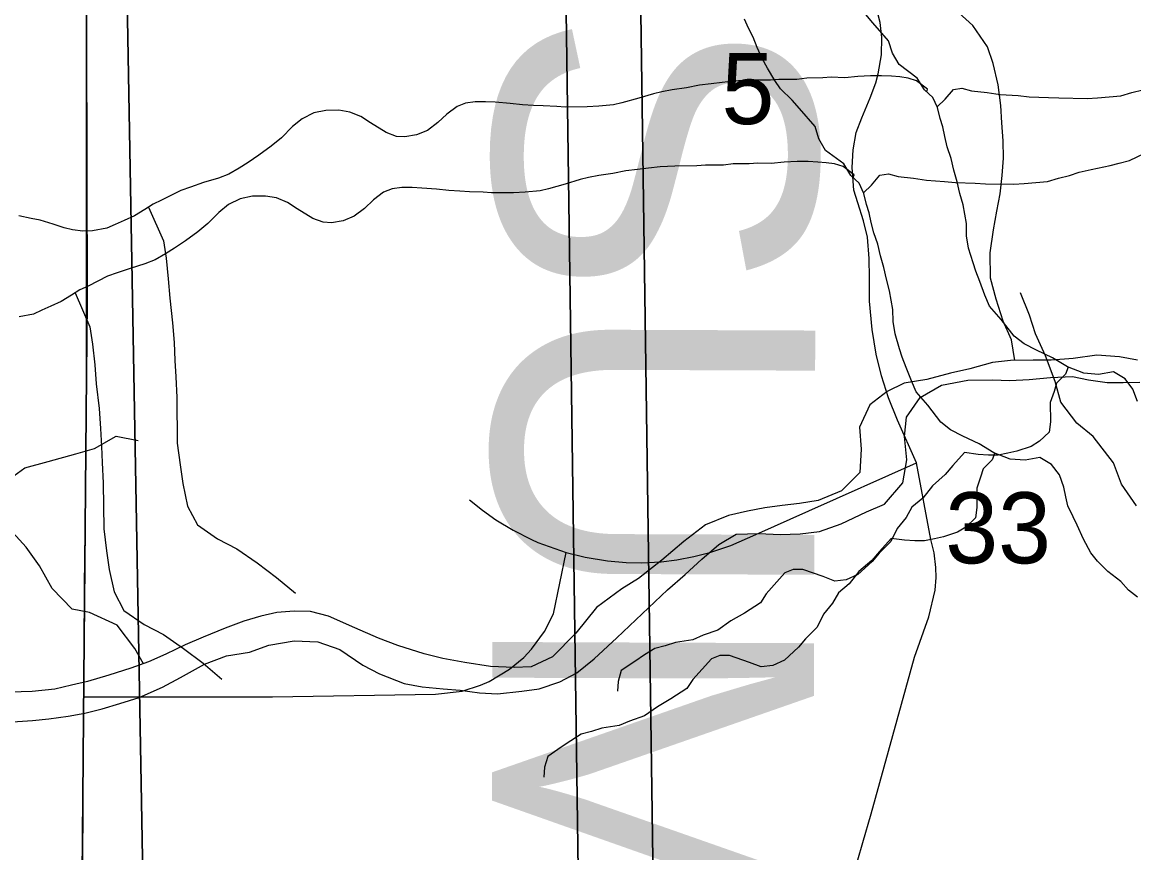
# Model space of a CAD drawing. Extents: x -21.1 to 50.3, y 0 to 22.1.
# Drawn here: x 6.485 to 7.139, y 16.143 to 16.632 of the extents above; entities that cross this region are included whole.
import ezdxf

# ---------------------------------------------------------------- set-up
doc = ezdxf.new("R2010")
doc.units = 0
for name, color, linetype in [('GM_X_County_Road', 7, 'Continuous'), ('GM_X_County_Text', 7, 'Continuous'), ('GM_X_Minor_River', 7, 'Continuous'), ('GM_X_Section', 7, 'Continuous'), ('GM_X_Section_Text', 7, 'Continuous'), ('GM_X_State_Route', 7, 'Continuous'), ('GM_X_Township_Road', 7, 'Continuous'), ('SH_Cut_Line', 7, 'Continuous')]:
    doc.layers.add(name, color=color, linetype=linetype)

msp = doc.modelspace()

# ---------------------------------------------------------------- linework, layer by layer
at = {"layer": 'GM_X_County_Road'}
for points in [[(6.52114, 16.23444), (6.5213, 16.26199), (6.5215, 16.29939), (6.52236, 16.36407), (6.52271, 16.39996), (6.52284, 16.44053), (6.52271, 16.56041), (6.52268, 16.59262), (6.52276, 16.63349), (6.52286, 16.64069), (6.52284, 16.6766), (6.52311, 16.71267), (6.52315, 16.75334), (6.52294, 16.79441), (6.5228, 16.83548), (6.52317, 16.84223), (6.5243, 16.84785), (6.52587, 16.85229), (6.52846, 16.85674)], [(6.52026, 16.0837), (6.52051, 16.137), (6.52074, 16.17106), (6.52098, 16.20504), (6.52114, 16.23444)]]:
    msp.add_lwpolyline(points, dxfattribs=at)
at = {"layer": 'GM_X_Minor_River'}
for points in [[(7.06943, 16.43253), (7.06738, 16.44462), (7.06252, 16.45565), (7.05843, 16.46857), (7.0551, 16.48111), (7.05482, 16.49591), (7.05681, 16.50956), (7.05878, 16.52055), (7.06074, 16.53078), (7.06195, 16.5414), (7.06278, 16.55163), (7.06247, 16.56188), (7.06178, 16.57251), (7.06108, 16.58276), (7.05965, 16.59491), (7.05669, 16.60745), (7.05334, 16.61733), (7.0447, 16.6299), (7.03451, 16.63907)], [(7.14173, 16.29323), (7.13638, 16.29738), (7.13179, 16.30229), (7.12414, 16.30833), (7.11802, 16.31438), (7.11418, 16.31929), (7.10995, 16.32725), (7.1061, 16.33558), (7.10379, 16.34051), (7.1007, 16.34695), (7.09953, 16.35226), (7.09836, 16.35796), (7.09566, 16.36516), (7.09105, 16.37121), (7.08418, 16.37535), (7.07543, 16.37379), (7.06667, 16.3745), (7.05714, 16.37825), (7.04835, 16.38352), (7.03881, 16.38802), (7.03156, 16.39178), (7.02582, 16.39631), (7.01816, 16.40615), (7.01126, 16.41408), (7.00856, 16.42053), (7.00547, 16.42849), (7.00315, 16.43455), (7.0016, 16.43948), (6.99889, 16.44821), (6.99771, 16.45542), (6.99767, 16.46264), (6.9957, 16.47364), (6.99376, 16.48047), (6.9922, 16.4873), (6.99026, 16.49413), (6.9887, 16.50095), (6.98638, 16.50778), (6.98482, 16.51385), (6.98365, 16.51954), (6.9821, 16.52447), (6.98054, 16.53092), (6.97784, 16.53698), (6.97286, 16.54152), (6.96864, 16.54833), (6.95794, 16.55625), (6.95409, 16.56307), (6.95177, 16.57027), (6.94257, 16.58086), (6.93836, 16.58577), (6.93147, 16.59257), (6.92802, 16.59749), (6.92379, 16.60469), (6.92071, 16.61037), (6.91763, 16.61681), (6.91531, 16.62288), (6.91262, 16.62818), (6.91031, 16.63349)], [(7.14165, 16.40847), (7.13894, 16.41567), (7.13434, 16.42173), (7.12747, 16.42587), (7.11872, 16.4243), (7.10996, 16.42501), (7.10043, 16.42876), (7.09164, 16.43403), (7.0821, 16.43854), (7.07485, 16.4423), (7.06911, 16.44682), (7.06145, 16.45666), (7.05455, 16.4646), (7.05185, 16.47104), (7.04876, 16.47901), (7.04644, 16.48507), (7.04489, 16.49), (7.04218, 16.49872), (7.041, 16.50593), (7.04096, 16.51315), (7.03899, 16.52416), (7.03705, 16.53098), (7.03549, 16.53781), (7.03355, 16.54464), (7.03199, 16.55147), (7.02966, 16.5583), (7.02811, 16.56437), (7.02693, 16.57006), (7.02538, 16.57499), (7.02383, 16.58144), (7.02113, 16.5875), (7.01615, 16.59203), (7.01193, 16.59885), (7.00123, 16.60677), (6.99738, 16.61358), (6.99506, 16.62079), (6.98586, 16.63138), (6.98165, 16.63629)], [(7.01759, 16.59073), (7.01805, 16.59242), (7.01156, 16.59733), (7.0066, 16.59882), (7.00165, 16.59955), (6.9967, 16.59991), (6.99099, 16.60025), (6.98452, 16.60022), (6.9769, 16.5998), (6.9693, 16.59899), (6.9613, 16.59933), (6.95636, 16.59892), (6.94684, 16.59887), (6.94113, 16.59808), (6.93619, 16.59806), (6.93048, 16.59802), (6.92553, 16.59762), (6.91259, 16.59755), (6.90384, 16.59712), (6.89699, 16.59632), (6.89052, 16.59553), (6.88368, 16.59473), (6.87607, 16.59317), (6.86771, 16.59198), (6.86162, 16.59081), (6.85668, 16.58965), (6.84794, 16.58694), (6.83806, 16.58423), (6.83312, 16.58306), (6.82437, 16.58225), (6.81752, 16.58184), (6.80458, 16.58177), (6.79963, 16.58212), (6.79163, 16.58245), (6.78592, 16.5828), (6.77945, 16.58315), (6.77221, 16.58387), (6.76345, 16.58458), (6.75774, 16.58493), (6.75165, 16.5849), (6.74595, 16.58411), (6.74101, 16.58218), (6.73494, 16.57759), (6.72965, 16.57262), (6.72358, 16.56803), (6.71712, 16.56534), (6.71028, 16.56416), (6.70533, 16.56451), (6.69922, 16.56676), (6.69006, 16.57241), (6.68433, 16.57617), (6.67784, 16.5788), (6.67136, 16.5799), (6.66375, 16.57986), (6.65653, 16.5783), (6.6497, 16.57485), (6.64402, 16.57026), (6.63758, 16.56376), (6.63152, 16.55879), (6.62432, 16.55343), (6.61787, 16.54922), (6.61256, 16.54577), (6.60649, 16.54232), (6.60041, 16.54001), (6.59167, 16.5373), (6.58407, 16.5346), (6.57838, 16.53267), (6.56699, 16.52691), (6.56205, 16.52461), (6.55712, 16.52154), (6.55105, 16.51771), (6.54498, 16.51502), (6.53966, 16.51271), (6.53473, 16.5104), (6.52636, 16.50884), (6.52065, 16.5088), (6.51456, 16.50953), (6.50961, 16.51064), (6.50312, 16.51289), (6.4955, 16.51513), (6.49016, 16.51624), (6.48292, 16.51772)], [(7.02365, 16.58183), (7.02837, 16.5864), (7.03328, 16.59213), (7.03823, 16.59291), (7.04394, 16.59142), (7.05308, 16.59033), (7.0607, 16.58923), (7.07136, 16.58853), (7.07784, 16.58781), (7.08926, 16.58749), (7.09535, 16.58714), (7.1121, 16.58686), (7.11819, 16.58727), (7.13189, 16.58848), (7.13835, 16.59042), (7.14481, 16.59197)], [(6.98036, 16.53132), (6.98508, 16.53589), (6.98999, 16.54161), (6.99494, 16.5424), (7.00065, 16.54091), (7.0098, 16.53982), (7.01742, 16.53872), (7.02808, 16.53802), (7.03455, 16.53729), (7.04597, 16.53697), (7.05206, 16.53663), (7.06881, 16.53634), (7.0749, 16.53675), (7.0886, 16.53797), (7.09506, 16.5399), (7.10152, 16.54146), (7.10722, 16.54339), (7.11444, 16.54495), (7.12547, 16.54729), (7.13079, 16.54883), (7.13687, 16.55039), (7.15092, 16.55692)], [(6.9743, 16.54021), (6.97477, 16.54191), (6.96827, 16.54681), (6.96331, 16.5483), (6.95836, 16.54903), (6.95341, 16.54939), (6.9477, 16.54974), (6.94123, 16.5497), (6.93362, 16.54928), (6.92601, 16.54848), (6.91801, 16.54882), (6.91307, 16.54841), (6.90355, 16.54836), (6.89785, 16.54757), (6.8929, 16.54754), (6.88719, 16.54751), (6.88224, 16.5471), (6.8693, 16.54703), (6.86055, 16.54661), (6.8537, 16.54581), (6.84724, 16.54501), (6.84039, 16.54422), (6.83278, 16.54265), (6.82442, 16.54147), (6.81833, 16.5403), (6.81339, 16.53913), (6.80465, 16.53642), (6.79477, 16.53371), (6.78983, 16.53254), (6.78108, 16.53174), (6.77423, 16.53132), (6.76129, 16.53125), (6.75634, 16.5316), (6.74835, 16.53194), (6.74263, 16.53229), (6.73616, 16.53263), (6.72892, 16.53335), (6.72017, 16.53407), (6.71445, 16.53441), (6.70836, 16.53438), (6.70266, 16.53359), (6.69772, 16.53166), (6.69166, 16.52707), (6.68636, 16.52211), (6.68029, 16.51751), (6.67384, 16.51482), (6.66699, 16.51364), (6.66204, 16.514), (6.65594, 16.51624), (6.64677, 16.52189), (6.64104, 16.52566), (6.63456, 16.52828), (6.62808, 16.52939), (6.62046, 16.52934), (6.61324, 16.52779), (6.60641, 16.52433), (6.60073, 16.51974), (6.59429, 16.51325), (6.58823, 16.50828), (6.58103, 16.50292), (6.57458, 16.49871), (6.56927, 16.49526), (6.5632, 16.4918), (6.55712, 16.48949), (6.54838, 16.48679), (6.54078, 16.48409), (6.53509, 16.48215), (6.5237, 16.4764), (6.51877, 16.47409), (6.51383, 16.47102), (6.50777, 16.46719), (6.50169, 16.4645), (6.49638, 16.46219), (6.49144, 16.45989), (6.48307, 16.45832)], [(6.55931, 16.5229), (6.56801, 16.50294), (6.56964, 16.49271), (6.57091, 16.48059), (6.5718, 16.46921), (6.57348, 16.45481), (6.57437, 16.44306), (6.57486, 16.43244), (6.57535, 16.42296), (6.57586, 16.41082), (6.57617, 16.38388), (6.57783, 16.371), (6.57947, 16.36001), (6.58227, 16.34676), (6.58808, 16.33582), (6.59993, 16.3276), (6.61137, 16.32165), (6.62322, 16.31343), (6.63469, 16.30482), (6.64579, 16.29545)], [(6.51602, 16.47238), (6.52472, 16.45243), (6.52635, 16.4422), (6.52762, 16.43007), (6.52851, 16.4187), (6.53019, 16.40429), (6.53108, 16.39254), (6.53158, 16.38192), (6.53206, 16.37244), (6.53258, 16.3603), (6.53288, 16.33337), (6.53454, 16.32048), (6.53618, 16.3095), (6.53898, 16.29625), (6.54479, 16.2853), (6.55664, 16.27708), (6.56808, 16.27113), (6.57993, 16.26291), (6.59141, 16.2543), (6.60251, 16.24493)], [(7.14098, 16.34694), (7.13214, 16.35978), (7.12747, 16.37227), (7.11557, 16.38773), (7.10601, 16.39562), (7.09641, 16.40807), (7.09326, 16.42019), (7.08743, 16.43534), (7.08162, 16.4482), (7.07811, 16.45918), (7.07268, 16.47243)], [(7.14168, 16.43278), (7.13107, 16.43474), (7.11779, 16.43558), (7.10374, 16.43377), (7.09083, 16.43271), (7.08021, 16.43278), (7.06692, 16.43248), (7.05629, 16.4314), (7.04299, 16.42769), (7.03158, 16.42511), (7.01752, 16.4214), (7.00422, 16.41921), (6.99433, 16.41433), (6.98403, 16.40643), (6.97787, 16.39319), (6.97892, 16.38028), (6.97807, 16.36663), (6.96738, 16.35569), (6.95368, 16.35008), (6.94266, 16.34826), (6.93241, 16.34718), (6.92215, 16.34573), (6.9119, 16.34389), (6.90087, 16.3413), (6.88718, 16.3357), (6.87459, 16.32591), (6.86161, 16.31499), (6.84788, 16.30407), (6.83798, 16.29806), (6.82311, 16.28715), (6.81086, 16.27205), (6.79711, 16.2581), (6.78455, 16.2521), (6.77468, 16.25178), (6.76064, 16.25225), (6.74548, 16.25462), (6.73259, 16.25697), (6.72161, 16.2597), (6.70608, 16.26472), (6.69472, 16.26897), (6.68073, 16.27512), (6.66521, 16.28205), (6.65461, 16.28477), (6.64512, 16.28483), (6.63487, 16.28413), (6.62537, 16.28192), (6.61548, 16.27894), (6.60445, 16.27483), (6.59151, 16.2696), (6.58086, 16.26512), (6.56943, 16.2595), (6.55916, 16.25501), (6.54889, 16.25128), (6.53596, 16.24718), (6.52341, 16.24347), (6.51391, 16.24125), (6.50403, 16.23903), (6.49074, 16.2376), (6.47784, 16.23729)], [(6.47924, 16.21983), (6.49101, 16.22052), (6.5005, 16.2216), (6.5119, 16.22305), (6.52177, 16.22489), (6.53204, 16.22748), (6.5423, 16.23045), (6.55371, 16.23417), (6.56741, 16.24016), (6.57807, 16.24578), (6.59217, 16.25366), (6.6051, 16.25852), (6.61878, 16.26071), (6.63019, 16.26481), (6.645, 16.26738), (6.65904, 16.26691), (6.67191, 16.26228), (6.68551, 16.25309), (6.69535, 16.2481), (6.70973, 16.24232), (6.72034, 16.24036), (6.73286, 16.23914), (6.74272, 16.23832), (6.75409, 16.23673), (6.76471, 16.23629), (6.77914, 16.23772), (6.7894, 16.23917), (6.80157, 16.24327), (6.81147, 16.24852), (6.82177, 16.2568), (6.83513, 16.26924), (6.86492, 16.29751), (6.87522, 16.30656), (6.88515, 16.3156), (6.89507, 16.32427), (6.90536, 16.33027), (6.91864, 16.33057), (6.93116, 16.33012), (6.94292, 16.33042), (6.95432, 16.33187), (6.96725, 16.33634), (6.98209, 16.34346), (6.99275, 16.34795), (7.00346, 16.3604), (7.00582, 16.37404), (7.0044, 16.38771), (7.00561, 16.39909), (7.01366, 16.4108), (7.02622, 16.41793), (7.0418, 16.42087), (7.05622, 16.42116), (7.06647, 16.42072), (7.07786, 16.42141), (7.09038, 16.42247), (7.10329, 16.42315), (7.11277, 16.42119), (7.12376, 16.41961), (7.13325, 16.41955), (7.14311, 16.41987)], [(7.10088, 16.42858), (7.09931, 16.42458), (7.09401, 16.41923), (7.09251, 16.41428), (7.09027, 16.40781), (7.09033, 16.39641), (7.0896, 16.39033), (7.08392, 16.38498), (7.07899, 16.38192), (7.07063, 16.37921), (7.06531, 16.37805), (7.05961, 16.37688), (7.0539, 16.37684), (7.04781, 16.37719), (7.03981, 16.37829), (7.033, 16.37065), (7.02846, 16.36531), (7.02088, 16.35881), (7.01522, 16.35156), (7.00878, 16.34621), (7.00538, 16.34011), (7.00009, 16.33363), (6.99633, 16.32601), (6.98951, 16.31913), (6.98536, 16.31417), (6.97702, 16.30653), (6.97019, 16.30345), (6.96334, 16.30266), (6.95648, 16.30528), (6.94465, 16.30939), (6.93894, 16.30936), (6.93401, 16.30744), (6.92304, 16.29522), (6.91964, 16.28988), (6.91016, 16.28375), (6.90219, 16.27915), (6.89461, 16.27379), (6.88587, 16.2707), (6.8798, 16.26801), (6.86953, 16.26644), (6.86345, 16.26451), (6.85737, 16.26295), (6.8513, 16.25912), (6.84561, 16.25529), (6.83765, 16.24993), (6.83578, 16.24346), (6.83543, 16.23776)], [(6.51651, 16.3776), (6.52743, 16.38067), (6.54027, 16.38801), (6.55319, 16.38547)], [(6.47351, 16.35981), (6.48644, 16.36933), (6.50013, 16.37315), (6.51651, 16.37764)], [(7.05759, 16.37807), (7.05602, 16.37406), (7.05072, 16.36871), (7.04922, 16.36377), (7.04698, 16.3573), (7.04704, 16.3459), (7.04631, 16.33982), (7.04063, 16.33447), (7.0357, 16.3314), (7.02735, 16.3287), (7.02202, 16.32753), (7.01632, 16.32636), (7.01061, 16.32633), (7.00452, 16.32668), (6.99652, 16.32777), (6.98971, 16.32014), (6.98517, 16.31479), (6.9776, 16.30829), (6.97193, 16.30105), (6.96549, 16.29569), (6.96209, 16.2896), (6.9568, 16.28311), (6.95304, 16.27549), (6.94623, 16.26862), (6.94207, 16.26365), (6.93374, 16.25601), (6.9269, 16.25294), (6.92006, 16.25214), (6.91319, 16.25476), (6.90137, 16.25888), (6.89566, 16.25885), (6.89072, 16.25692), (6.87975, 16.2447), (6.87635, 16.23937), (6.86687, 16.23324), (6.8589, 16.22864), (6.85132, 16.22328), (6.84258, 16.22019), (6.83651, 16.2175), (6.82624, 16.21592), (6.82016, 16.21399), (6.81408, 16.21244), (6.80801, 16.20861), (6.80232, 16.20478), (6.79436, 16.19941), (6.79249, 16.19295), (6.79214, 16.18725)], [(6.55635, 16.25399), (6.55125, 16.26302), (6.54071, 16.27675), (6.52444, 16.28405), (6.51421, 16.28601), (6.50252, 16.29823), (6.49502, 16.31155), (6.48713, 16.3226), (6.47545, 16.33558)]]:
    msp.add_lwpolyline(points, dxfattribs=at)
at = {"layer": 'GM_X_Section'}
for points in [[(5.83147, 16.97938), (6.84408, 16.99761), (6.85861, 15.97246), (5.84702, 15.96751)], [(6.84408, 16.99761), (7.38497, 16.99642), (7.85852, 16.9825), (7.86729, 15.96487), (7.36725, 15.97553), (6.85861, 15.97246)], [(5.78818, 16.92886), (6.8008, 16.94709), (6.81532, 15.92194), (5.80373, 15.91699)], [(6.8008, 16.94709), (7.34169, 16.9459), (7.81523, 16.93198), (7.824, 15.91436), (7.32396, 15.92501), (6.81532, 15.92194)], [(6.54146, 16.94121), (6.55964, 15.91994), (6.50469, 15.92066), (5.53343, 15.91957), (5.52017, 16.94387)], [(7.56617, 16.93816), (7.57297, 15.92106), (7.52522, 15.9214), (6.55964, 15.91994), (6.54146, 16.94121)]]:
    msp.add_lwpolyline(points, close=True, dxfattribs=at)
at = {"layer": 'GM_X_State_Route'}
for points in [[(8.9, 14.1), (8.9, 17.84218), (8.25757, 17.83124), (7.86638, 17.82395), (7.58368, 17.81946), (6.90933, 17.81425), (6.69997, 17.81193), (6.66406, 17.81203), (6.52196, 17.81036), (6.52053, 17.72081), (6.52013, 17.69645), (6.52222, 16.85672), (6.52315, 16.46813), (6.52123, 16.24517), (6.51982, 16.08256), (6.51595, 15.49226), (6.51465, 15.30312), (6.514, 15.09364), (6.51464, 15.03489), (6.5142, 14.9441), (6.51283, 14.60317)], [(6.51283, 14.60317), (6.5142, 14.9441), (6.51464, 15.03489), (6.514, 15.09364), (6.51465, 15.30312), (6.51595, 15.49226), (6.51982, 16.08256), (6.52123, 16.24517), (6.52315, 16.46813), (6.52222, 16.85672), (6.52013, 17.69645), (6.52053, 17.72081), (6.52196, 17.81036), (5.33072, 17.79178), (3.94025, 17.77171), (3.44154, 17.76826), (3.3026, 17.76263), (3.03298, 17.75833), (2.73209, 17.75291), (2.42851, 17.74626), (2.1, 17.74017), (2.1, 14.1)]]:
    msp.add_lwpolyline(points, dxfattribs=at)
at = {"layer": 'GM_X_Township_Road'}
for points in [[(7.01151, 16.3723), (7.0003, 16.39738), (6.99501, 16.41051), (6.99084, 16.42355), (6.98774, 16.43625), (6.98531, 16.4508), (6.98393, 16.46744), (6.98375, 16.48129), (6.98369, 16.49259), (6.98258, 16.50511), (6.98022, 16.51484), (6.9769, 16.52542), (6.97456, 16.53291), (6.97363, 16.54621), (6.97421, 16.55654), (6.97594, 16.56689), (6.97941, 16.57543), (6.98424, 16.58731), (6.98752, 16.59599), (6.989, 16.60126), (6.99084, 16.61261), (6.99102, 16.62284), (6.99006, 16.63164), (6.98725, 16.64291)], [(6.74837, 16.35045), (6.75588, 16.34436), (6.76383, 16.3387), (6.77395, 16.33255), (6.78478, 16.32708), (6.78857, 16.32542), (6.80523, 16.31949), (6.81644, 16.31669), (6.82957, 16.31452), (6.84046, 16.31362), (6.84929, 16.31346), (6.86118, 16.31406), (6.87043, 16.31518), (6.88032, 16.31702), (6.88988, 16.31946), (6.90227, 16.32366), (6.9169, 16.32998), (6.94817, 16.34396), (7.01151, 16.3723)], [(6.9604, 16.05883), (6.96439, 16.08933), (6.96807, 16.10776), (6.97994, 16.1487), (6.98486, 16.16549), (7.01025, 16.25776), (7.01875, 16.28162), (7.02258, 16.29729), (7.02312, 16.30482), (7.02299, 16.3107), (7.02194, 16.3192), (7.01996, 16.32719), (7.01151, 16.3723)], [(6.52114, 16.23444), (6.63224, 16.23441), (6.72827, 16.23609), (6.74388, 16.23787), (6.75477, 16.24135), (6.75982, 16.24349), (6.7719, 16.25075), (6.78035, 16.25772), (6.78488, 16.26246), (6.79244, 16.27291), (6.79771, 16.28329), (6.80523, 16.31949)]]:
    msp.add_lwpolyline(points, dxfattribs=at)
at = {"layer": 'SH_Cut_Line'}
for points in [[(6.52955, 20.9), (2.1, 20.9), (2.1, 14.1), (6.50995, 14.1), (6.5113, 14.24348), (6.51114, 14.29418), (6.513, 14.41466), (6.51283, 14.60317), (6.5142, 14.9441), (6.51464, 15.03489), (6.514, 15.09364), (6.51465, 15.30312), (6.51595, 15.49226), (6.51982, 16.08256), (6.52123, 16.24517), (6.52315, 16.46813), (6.52222, 16.85672), (6.52013, 17.69645), (6.52053, 17.72081), (6.52196, 17.81036), (6.52225, 18.35692), (6.52255, 18.97782), (6.52273, 19.34666), (6.52977, 20.39859)], [(6.50995, 14.1), (8.9, 14.1), (8.9, 20.9), (6.52955, 20.9), (6.52977, 20.39859), (6.52273, 19.34666), (6.52255, 18.97782), (6.52225, 18.35692), (6.52196, 17.81036), (6.52053, 17.72081), (6.52013, 17.69645), (6.52222, 16.85672), (6.52315, 16.46813), (6.52123, 16.24517), (6.51982, 16.08256), (6.51595, 15.49226), (6.51465, 15.30312), (6.514, 15.09364), (6.51464, 15.03489), (6.5142, 14.9441), (6.51283, 14.60317), (6.513, 14.41466), (6.51114, 14.29418), (6.5113, 14.24348)]]:
    msp.add_lwpolyline(points, close=True, dxfattribs=at)

# ---------------------------------------------------------------- texts
at = {"layer": 'GM_X_County_Text'}
msp.add_text('SUMMIT COUNTY', height=0.1893939, rotation=269.77943, dxfattribs=at).set_placement((6.76324, 16.63937))
at = {"layer": 'GM_X_Section_Text'}
for s, height, p in [('5', 0.04186, (6.89669, 16.57176)), ('33', 0.041856, (7.02845, 16.31307))]:
    msp.add_text(s, height=height, rotation=0.00001, dxfattribs=at).set_placement(p)

doc.saveas('drawing.dxf')
